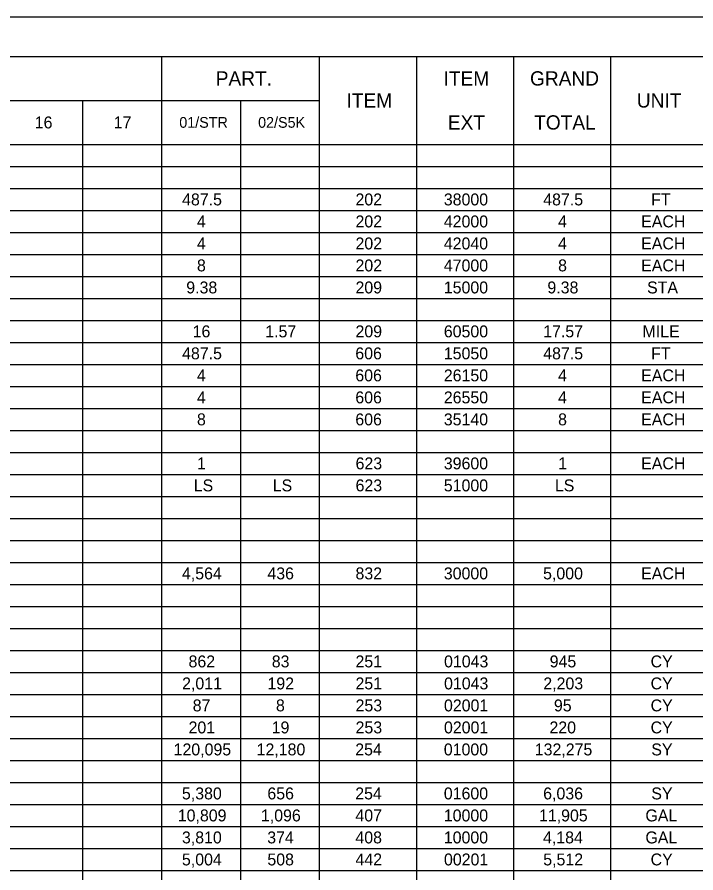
# Model space of a CAD drawing. Extents: x 0 to 34, y 0 to 22.
# Drawn here: x 8.71 to 17.34, y 11.11 to 22 of the extents above; entities that cross this region are included whole.
import ezdxf

# ---------------------------------------------------------------- set-up
doc = ezdxf.new("R2010")
doc.units = 0
for name, color, linetype in [('SH_Border', 7, 'Continuous'), ('SH_Cut_Line', 7, 'Continuous'), ('SH_Data', 7, 'Continuous')]:
    doc.layers.add(name, color=color, linetype=linetype)

msp = doc.modelspace()

# ---------------------------------------------------------------- linework, layer by layer
at = {"layer": 'SH_Border'}
msp.add_lwpolyline([(1.5, 21.5), (33.5, 21.5), (33.5, 0.5), (1.5, 0.5)], close=True, dxfattribs=at)
at = {"layer": 'SH_Cut_Line'}
msp.add_lwpolyline([(0, 0), (34, 0), (34, 22), (0, 22)], close=True, dxfattribs=at)
at = {"layer": 'SH_Data'}
for p, q in [((1.5, 21.5), (32.001, 21.5)), ((10.542, 21.5), (10.542, 0.502)), ((12.551, 21.5), (12.551, 0.502)), ((13.786, 21.5), (13.786, 0.502)), ((15.021, 21.5), (15.021, 0.502)), ((16.256, 21.5), (16.256, 0.502)), ((1.5, 20.94), (12.551, 20.94)), ((9.537, 20.94), (9.537, 0.502)), ((11.546, 20.94), (11.546, 0.502)), ((1.5, 20.38), (32.001, 20.38)), ((1.5, 20.1), (32.001, 20.1)), ((1.5, 19.82), (32.001, 19.82)), ((1.5, 19.54), (32.001, 19.54)), ((1.5, 19.26), (32.001, 19.26)), ((1.5, 18.98), (32.001, 18.98)), ((1.5, 18.7), (32.001, 18.7)), ((1.5, 18.42), (32.001, 18.42)), ((1.5, 18.14), (32.001, 18.14)), ((1.5, 17.86), (32.001, 17.86)), ((1.5, 17.58), (32.001, 17.58)), ((1.5, 17.3), (32.001, 17.3)), ((1.5, 17.02), (32.001, 17.02)), ((1.5, 16.74), (32.001, 16.74)), ((1.5, 16.46), (32.001, 16.46)), ((1.5, 16.18), (32.001, 16.18)), ((1.5, 15.9), (32.001, 15.9)), ((1.5, 15.62), (32.001, 15.62)), ((1.5, 15.34), (32.001, 15.34)), ((1.5, 15.061), (32.001, 15.061)), ((1.5, 14.781), (32.001, 14.781)), ((1.5, 14.501), (32.001, 14.501)), ((1.5, 14.221), (32.001, 14.221)), ((1.5, 13.941), (32.001, 13.941)), ((1.5, 13.661), (32.001, 13.661)), ((1.5, 13.381), (32.001, 13.381)), ((1.5, 13.101), (32.001, 13.101)), ((1.5, 12.821), (32.001, 12.821)), ((1.5, 12.541), (32.001, 12.541)), ((1.5, 12.261), (32.001, 12.261)), ((1.5, 11.981), (32.001, 11.981)), ((1.5, 11.701), (32.001, 11.701)), ((1.5, 11.421), (32.001, 11.421)), ((1.5, 11.141), (32.001, 11.141))]:
    msp.add_line(p, q, dxfattribs=at)

# ---------------------------------------------------------------- texts
for s, height, p in [('PART.', 0.1818, (11.233, 21.129)), ('ITEM', 0.1818, (14.132, 21.129)), ('GRAND', 0.1818, (15.232, 21.129)), ('ITEM', 0.1818, (12.897, 20.849)), ('UNIT', 0.1818, (16.591, 20.849)), ('16', 0.1515, (8.93, 20.584)), ('17', 0.1515, (9.935, 20.584)), ('01/STR', 0.1364, (10.769, 20.592)), ('02/S5K', 0.1364, (11.772, 20.592)), ('EXT', 0.1818, (14.186, 20.569)), ('TOTAL', 0.1818, (15.284, 20.569)), ('487.5', 0.1515, (10.805, 19.604)), ('202', 0.1515, (13.011, 19.604)), ('38000', 0.1515, (14.135, 19.604)), ('487.5', 0.1515, (15.4, 19.604)), ('FT', 0.1515, (16.773, 19.604)), ('4', 0.152, (10.993, 19.324)), ('202', 0.1515, (13.011, 19.324)), ('42000', 0.1515, (14.135, 19.324)), ('4', 0.152, (15.588, 19.324)), ('EACH', 0.1515, (16.646, 19.324)), ('4', 0.152, (10.993, 19.044)), ('202', 0.1515, (13.011, 19.044)), ('42040', 0.1515, (14.135, 19.044)), ('4', 0.152, (15.588, 19.044)), ('EACH', 0.1515, (16.646, 19.044)), ('8', 0.152, (10.994, 18.764)), ('202', 0.1515, (13.011, 18.764)), ('47000', 0.1515, (14.135, 18.764)), ('8', 0.152, (15.589, 18.764)), ('EACH', 0.1515, (16.646, 18.764)), ('9.38', 0.1515, (10.858, 18.484)), ('209', 0.1515, (13.011, 18.484)), ('15000', 0.1515, (14.135, 18.484)), ('9.38', 0.1515, (15.453, 18.484)), ('STA', 0.1515, (16.721, 18.484)), ('16', 0.1515, (10.939, 17.925)), ('209', 0.1515, (13.011, 17.925)), ('60500', 0.1515, (14.135, 17.925)), ('1.57', 0.1515, (11.863, 17.925)), ('17.57', 0.1515, (15.399, 17.925)), ('MILE', 0.1515, (16.663, 17.925)), ('487.5', 0.1515, (10.805, 17.645)), ('606', 0.1515, (13.009, 17.645)), ('15050', 0.1515, (14.135, 17.645)), ('487.5', 0.1515, (15.4, 17.645)), ('FT', 0.1515, (16.773, 17.645)), ('4', 0.152, (10.993, 17.365)), ('606', 0.1515, (13.009, 17.365)), ('26150', 0.1515, (14.135, 17.365)), ('4', 0.152, (15.588, 17.365)), ('EACH', 0.1515, (16.646, 17.365)), ('4', 0.152, (10.993, 17.085)), ('606', 0.1515, (13.009, 17.085)), ('26550', 0.1515, (14.135, 17.085)), ('4', 0.152, (15.588, 17.085)), ('EACH', 0.1515, (16.646, 17.085)), ('8', 0.152, (10.994, 16.805)), ('606', 0.1515, (13.009, 16.805)), ('35140', 0.1515, (14.135, 16.805)), ('8', 0.152, (15.589, 16.805)), ('EACH', 0.1515, (16.646, 16.805)), ('1', 0.152, (10.995, 16.245)), ('623', 0.1515, (13.012, 16.245)), ('39600', 0.1515, (14.135, 16.245)), ('1', 0.152, (15.59, 16.245)), ('EACH', 0.1515, (16.646, 16.245)), ('LS', 0.1515, (10.953, 15.965)), ('LS', 0.1515, (11.958, 15.965)), ('623', 0.1515, (13.012, 15.965)), ('51000', 0.1515, (14.135, 15.965)), ('LS', 0.1515, (15.548, 15.965)), ('4,564', 0.1515, (10.803, 14.845)), ('436', 0.1515, (11.89, 14.845)), ('832', 0.1515, (13.011, 14.845)), ('30000', 0.1515, (14.135, 14.845)), ('5,000', 0.1515, (15.398, 14.845)), ('EACH', 0.1515, (16.646, 14.845)), ('862', 0.1515, (10.887, 13.725)), ('83', 0.1515, (11.946, 13.725)), ('251', 0.1515, (13.011, 13.725)), ('01043', 0.1515, (14.138, 13.725)), ('945', 0.1515, (15.482, 13.725)), ('CY', 0.1515, (16.766, 13.725)), ('2,011', 0.1515, (10.805, 13.445)), ('192', 0.1515, (11.891, 13.445)), ('251', 0.1515, (13.011, 13.445)), ('01043', 0.1515, (14.138, 13.445)), ('2,203', 0.1515, (15.401, 13.445)), ('CY', 0.1515, (16.766, 13.445)), ('87', 0.1515, (10.94, 13.165)), ('8', 0.152, (11.999, 13.165)), ('253', 0.1515, (13.012, 13.165)), ('02001', 0.1515, (14.137, 13.165)), ('95', 0.1515, (15.536, 13.165)), ('CY', 0.1515, (16.766, 13.165)), ('201', 0.1515, (10.887, 12.885)), ('19', 0.1515, (11.945, 12.885)), ('253', 0.1515, (13.012, 12.885)), ('02001', 0.1515, (14.137, 12.885)), ('220', 0.1515, (15.479, 12.885)), ('CY', 0.1515, (16.766, 12.885)), ('120,095', 0.1515, (10.697, 12.605)), ('12,180', 0.1515, (11.753, 12.605)), ('254', 0.1515, (13.008, 12.605)), ('01000', 0.1515, (14.135, 12.605)), ('132,275', 0.1515, (15.292, 12.605)), ('SY', 0.1515, (16.775, 12.605)), ('5,380', 0.1515, (10.803, 12.045)), ('656', 0.1515, (11.89, 12.045)), ('254', 0.1515, (13.008, 12.045)), ('01600', 0.1515, (14.135, 12.045)), ('6,036', 0.1515, (15.399, 12.045)), ('SY', 0.1515, (16.775, 12.045)), ('10,809', 0.1515, (10.75, 11.765)), ('1,096', 0.1515, (11.808, 11.765)), ('407', 0.1515, (13.01, 11.765)), ('10000', 0.1515, (14.135, 11.765)), ('11,905', 0.1515, (15.346, 11.765)), ('GAL', 0.1515, (16.7, 11.765)), ('3,810', 0.1515, (10.803, 11.485)), ('374', 0.1515, (11.888, 11.485)), ('408', 0.1515, (13.01, 11.485)), ('10000', 0.1515, (14.135, 11.485)), ('4,184', 0.1515, (15.397, 11.485)), ('GAL', 0.1515, (16.7, 11.485)), ('5,004', 0.1515, (10.803, 11.205)), ('508', 0.1515, (11.89, 11.205)), ('442', 0.1515, (13.011, 11.205)), ('00201', 0.1515, (14.137, 11.205)), ('5,512', 0.1515, (15.4, 11.205)), ('CY', 0.1515, (16.766, 11.205))]:
    msp.add_text(s, height=height, dxfattribs=at).set_placement(p)

doc.saveas('drawing.dxf')
